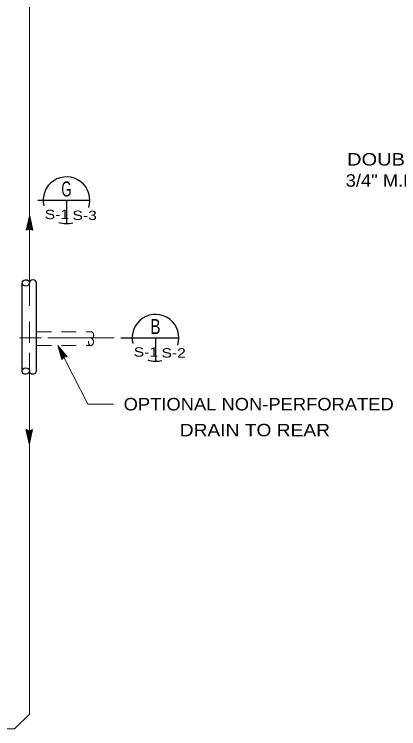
# Model space of a CAD drawing. Extents: x -24.3 to 17.7, y -17.6 to 12.4.
# Drawn here: x -5.03 to -1.17, y 0.83 to 7.99 of the extents above; entities that cross this region are included whole.
import ezdxf
from ezdxf.enums import TextEntityAlignment as Align

# ---------------------------------------------------------------- set-up
doc = ezdxf.new("R2010")
doc.units = 0
doc.header["$LTSCALE"] = 0.05
doc.linetypes.add('MEDIUM_DASHED', pattern=[4.5, 3, -1.5])
doc.layers.add('1', color=7, linetype='Continuous', lineweight=13)
doc.layers.add('2', color=7, linetype='Continuous', lineweight=13)

msp = doc.modelspace()

# ---------------------------------------------------------------- linework, layer by layer
at = {"layer": '1', "lineweight": 25}
for p, q in [((-4.87569, 5.9694), (-4.90669, 5.8254)), ((-4.87569, 5.9694), (-4.84469, 5.8254)), ((-4.87569, 5.9324), (-4.89569, 5.8384)), ((-4.87569, 5.8964), (-4.88469, 5.8514)), ((-4.87569, 5.9324), (-4.85569, 5.8384)), ((-4.87569, 5.8964), (-4.86569, 5.8514)), ((-4.87569, 5.8474), (-4.89569, 5.8384)), ((-4.87569, 5.8554), (-4.88469, 5.8514)), ((-4.86569, 5.8514), (-4.87569, 5.8554)), ((-4.85569, 5.8384), (-4.87569, 5.8474)), ((-4.94869, 4.4054), (-4.94869, 5.2954)), ((-4.80569, 4.4134), (-4.80569, 5.2974)), ((-4.87569, 3.6844), (-4.90669, 3.8284)), ((-4.87569, 3.7214), (-4.89569, 3.8154)), ((-4.89569, 3.8154), (-4.87569, 3.8064)), ((-4.87569, 3.7574), (-4.88569, 3.8024)), ((-4.88569, 3.8024), (-4.87569, 3.7984)), ((-4.87569, 3.6844), (-4.84469, 3.8284)), ((-4.87569, 3.7214), (-4.85569, 3.8154)), ((-4.87569, 3.8064), (-4.85569, 3.8154)), ((-4.87569, 3.7574), (-4.86669, 3.8024)), ((-4.87569, 3.7984), (-4.86669, 3.8024))]:
    msp.add_line(p, q, dxfattribs=at)
at = {"layer": '1'}
for p, q in [((-4.87569, 4.6954), (-4.87569, 4.9104)), ((-4.97569, 4.7464), (-4.75569, 4.7464)), ((-4.68969, 4.7464), (-4.02569, 4.7464)), ((-4.58969, 4.6694), (-4.49669, 4.5554)), ((-4.58969, 4.6694), (-4.55169, 4.5274)), ((-4.87569, 3.6844), (-4.87569, 4.5954)), ((-4.57269, 4.6364), (-4.51269, 4.5614)), ((-4.57269, 4.6364), (-4.54769, 4.5434)), ((-4.55669, 4.6044), (-4.54369, 4.5604)), ((-4.55669, 4.6044), (-4.52769, 4.5684)), ((-4.53469, 4.5604), (-4.54769, 4.5434)), ((-4.53769, 4.5674), (-4.54369, 4.5604)), ((-4.52769, 4.5684), (-4.53769, 4.5674)), ((-4.51269, 4.5614), (-4.53469, 4.5604)), ((-4.87569, 0.9724), (-4.87569, 3.6824)), ((-5.02369, 0.8254), (-4.87569, 0.9724)), ((-8.66569, 0.8254), (-5.02369, 0.8254))]:
    msp.add_line(p, q, dxfattribs=at)
at = {"layer": '1', "linetype": 'MEDIUM_DASHED'}
for p, q in [((-4.80569, 4.8074), (-4.25469, 4.8074)), ((-4.80569, 4.6694), (-4.26069, 4.6694))]:
    msp.add_line(p, q, dxfattribs=at)
at = {"layer": '1'}
for points in [[(-4.87569, 5.0674), (-4.87569, 5.9694), (-4.87569, 8.5174)], [(-4.58969, 4.6694), (-4.28969, 4.0804), (-4.03169, 4.0804)], [(-4.49669, 4.5554), (-4.53069, 4.5534), (-4.55169, 4.5274)]]:
    msp.add_lwpolyline(points, dxfattribs=at)
at = {"layer": '1', "lineweight": 25}
for points in [[(-4.84469, 5.8254), (-4.87569, 5.8394), (-4.90669, 5.8254)], [(-4.90669, 3.8284), (-4.87569, 3.8144), (-4.84469, 3.8284)]]:
    msp.add_lwpolyline(points, dxfattribs=at)
for centre in [(-4.91219, 5.2974), (-4.91219, 4.4134)]:
    msp.add_ellipse(centre, major_axis=(0.0365, 0.002), ratio=0.876354, dxfattribs=at)
for centre, major_axis, start_param, end_param in [((-4.84069, 5.2984), (-0.035, 0.001), 3.1415927, 6.2831853), ((-4.84069, 4.4124), (-0.035, -0.001), 0, 3.1415927)]:
    msp.add_ellipse(centre, major_axis=major_axis, ratio=0.828971, start_param=start_param, end_param=end_param, dxfattribs=at)
at = {"layer": '1', "linetype": 'MEDIUM_DASHED'}
msp.add_ellipse((-4.25719, 4.7734), major_axis=(0.0015, -0.034), ratio=0.749111, start_param=6.2831853, end_param=9.424778, dxfattribs=at)
msp.add_ellipse((-4.25819, 4.7044), major_axis=(0.0025, 0.035), ratio=0.70437, dxfattribs=at)
at = {"layer": '2', "lineweight": 25}
for p, q in [((-4.79269, 6.1264), (-4.73769, 6.1264)), ((-4.73769, 6.1264), (-4.26969, 6.1264)), ((-4.50369, 6.1264), (-4.50369, 5.8924)), ((-3.95969, 4.7464), (-3.84569, 4.7464)), ((-3.84569, 4.7464), (-3.37769, 4.7464)), ((-3.61169, 4.7464), (-3.61169, 4.5124))]:
    msp.add_line(p, q, dxfattribs=at)
for centre, start, end in [((-4.50394, 6.12615), 341.96976, 193.81208), ((-4.50394, 6.12615), 251.04049, 285.74671), ((-3.61194, 4.74615), 341.96976, 193.81208), ((-3.61194, 4.74615), 251.04049, 285.74671)]:
    msp.add_arc(centre, 0.23438, start, end, dxfattribs=at)

# ---------------------------------------------------------------- texts
at = {"layer": '1', "width": 1.2}
msp.add_text('DOUBLE NUT -', height=0.125, dxfattribs=at).set_placement((-0.27669, 6.4744), align=Align.RIGHT)
at = {"layer": '1'}
for s, width, p in [('3/4" M.P. NUTS', 1.1, (-1.05519, 6.2624)), ('DRAIN TO REAR', 1.15, (-2.61619, 3.7584))]:
    msp.add_text(s, height=0.125, dxfattribs=dict(at, width=width)).set_placement(p, align=Align.CENTER)
at = {"layer": '1', "width": 1.1}
msp.add_text('OPTIONAL NON-PERFORATED', height=0.125, dxfattribs=at).set_placement((-3.93169, 4.0184))
at = {"layer": '2'}
for s, height, width, p in [('G', 0.15, 0.65, (-4.50469, 6.1644)), ('S-1', 0.094, 1.25, (-4.60019, 5.9374)), ('S-3', 0.094, 1.25, (-4.32219, 5.9284)), ('B', 0.15, 0.75, (-3.61269, 4.7844)), ('S-1', 0.094, 1.25, (-3.70819, 4.5574)), ('S-2', 0.094, 1.25, (-3.43019, 4.5484))]:
    msp.add_text(s, height=height, dxfattribs=dict(at, width=width)).set_placement(p, align=Align.CENTER)

doc.saveas('drawing.dxf')
